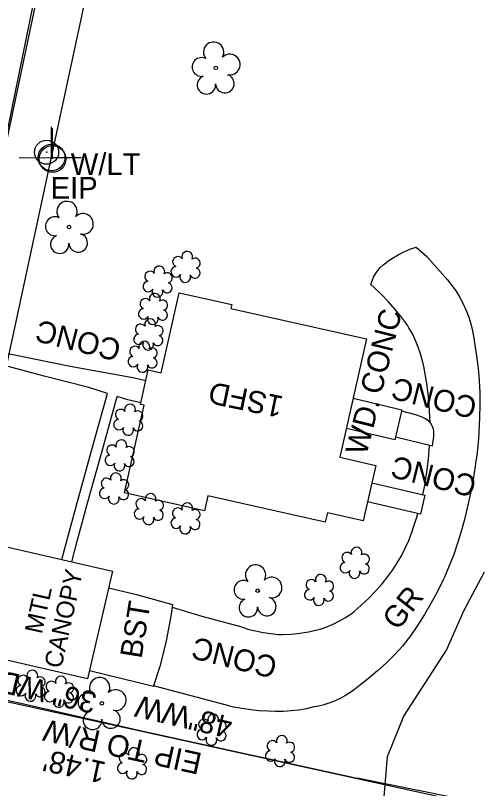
# Model space of a CAD drawing. Extents: x 1614611 to 1617571, y 898867 to 905462.
# Drawn here: x 1616539.4 to 1616625, y 901015.6 to 901157.4 of the extents above; entities that cross this region are included whole.
import ezdxf

# ---------------------------------------------------------------- set-up
doc = ezdxf.new("R2010")
doc.units = 0
for name, color, linetype in [('Exist Building', 7, 'Continuous'), ('Exist Building Metal Canopy', 7, 'Continuous'), ('Exist Building Metal Canopy Text', 7, 'Continuous'), ('Exist Building Text', 7, 'Continuous'), ('Exist Drainage Structure Drop Inlet CELL', 7, 'Continuous'), ('Exist Other Culture Area Outline', 7, 'Continuous'), ('Exist Other Culture Area Outline Text', 7, 'Continuous'), ('Exist Other Culture Fence Line', 7, 'Continuous'), ('Exist Other Culture Fence Line Text', 7, 'Continuous'), ('Exist Plan Preparation Watershed Yellow', 7, 'Continuous'), ('Exist Roads EOP Other Text', 7, 'Continuous'), ('Exist Roads Soil', 7, 'Continuous'), ('Exist Roads Soil Text', 7, 'Continuous'), ('Exist Utilities Power Joint Use Telephone CELL', 7, 'Continuous'), ('Exist Utilities Power Pole CELL', 7, 'Continuous'), ('Exist Utilities Power Pole Text', 7, 'Continuous'), ('Exist Utilities Sanitary Sewer UG Line', 7, 'Continuous'), ('Exist Utilities Telephone UG FO SUE LOS B', 7, 'Continuous'), ('Exist Vegetation Shrub CELL', 7, 'Continuous'), ('Exist Vegetation Tree CELL', 7, 'Continuous'), ('Exist Vegetation Woods Line', 7, 'Continuous'), ('Prop Drainage Structure Catch Basin Open Throat 4 Label', 7, 'Continuous'), ('Prop Drainage Structure Pipe Alternate 30in Label', 7, 'Continuous'), ('Prop Earthen Structure Head Ditch Label', 7, 'Continuous'), ('Scratch_Level_1', 7, 'Continuous')]:
    doc.layers.add(name, color=color, linetype=linetype)

msp = doc.modelspace()

# ---------------------------------------------------------------- linework, layer by layer
at = {"layer": 'Exist Building'}
msp.add_lwpolyline([(1616603.72, 901098.1), (1616598.85, 901076.36), (1616605.42, 901074.89), (1616603.14, 901064.73), (1616596.57, 901066.21), (1616596.19, 901064.49), (1616574.67, 901069.31), (1616574.06, 901066.58), (1616559.42, 901069.86), (1616563.02, 901085.9), (1616562.3, 901086.06), (1616563.71, 901092.37), (1616566.12, 901091.83), (1616569.41, 901106.5), (1616579.03, 901104.35), (1616578.87, 901103.67)], close=True, dxfattribs=at)
at = {"layer": 'Exist Building Metal Canopy'}
msp.add_lwpolyline([(1616537.54, 901060.03), (1616557.18, 901055.5), (1616552.62, 901035.75), (1616532.98, 901040.28)], close=True, dxfattribs=at)
at = {"layer": 'Exist Other Culture Area Outline'}
for points in [[(1616556.26, 901088.08), (1616552.83, 901089.13), (1616544.7, 901091.24), (1616535.73, 901093.64), (1616536.2, 901095.73), (1616549.45, 901093.07), (1616560.94, 901090.97), (1616563.28, 901090.43)], [(1616547.93, 901057.63), (1616548.95, 901061.47), (1616550.91, 901068.69), (1616553.74, 901078.87), (1616556.26, 901088.08)], [(1616549.74, 901057.22), (1616550.74, 901060.99), (1616552.7, 901068.2), (1616555.52, 901078.38), (1616558.03, 901087.54)], [(1616562.37, 901086.37), (1616560.02, 901086.92), (1616558.03, 901087.54)], [(1616601.28, 901087.19), (1616610.24, 901085.06), (1616608.93, 901079.54), (1616600.04, 901081.66)], [(1616609.06, 901080.1), (1616615.8, 901078.48), (1616616.05, 901080.2), (1616616.09, 901080.69), (1616616.06, 901081.19), (1616615.95, 901081.68), (1616615.76, 901082.14), (1616615.5, 901082.57), (1616615.17, 901082.95), (1616615.13, 901082.99), (1616614.55, 901083.39), (1616613.93, 901083.73), (1616613.28, 901083.99), (1616612.75, 901084.15), (1616610.18, 901084.81)], [(1616604.7, 901071.67), (1616614.41, 901069.45), (1616613.61, 901065.97), (1616603.92, 901068.19)]]:
    msp.add_lwpolyline(points, dxfattribs=at)
at = {"layer": 'Exist Other Culture Fence Line'}
for points in [[(1616524.45, 901034.81), (1616540.38, 901031.29), (1616562.24, 901026.28), (1616602, 901017.55)], [(1616668.58, 901003.27), (1616635.85, 901010.68), (1616602, 901017.55)]]:
    msp.add_lwpolyline(points, dxfattribs=at)
at = {"layer": 'Exist Plan Preparation Watershed Yellow'}
for radius in [2.2, 0.0707]:
    msp.add_circle((1616545.12, 901132.28), radius, dxfattribs=at)
at = {"layer": 'Exist Roads Soil'}
for points in [[(1616615.4, 901082.69), (1616615.37, 901083.78), (1616615.24, 901085.94), (1616615.03, 901088.09), (1616614.74, 901090.23), (1616614.37, 901092.36), (1616614.29, 901092.79), (1616614.01, 901094.07), (1616613.65, 901095.34), (1616613.23, 901096.58), (1616612.72, 901097.79), (1616612.15, 901098.97), (1616611.51, 901100.11), (1616611.23, 901100.56), (1616610.12, 901102.03), (1616608.96, 901103.47), (1616607.74, 901104.85), (1616606.46, 901106.2), (1616605.13, 901107.49), (1616604.55, 901108.02), (1616604.75, 901108.71), (1616605.03, 901109.38), (1616605.37, 901110.02), (1616605.79, 901110.62), (1616606.26, 901111.17), (1616606.79, 901111.66), (1616607.37, 901112.1), (1616607.48, 901112.17), (1616608.48, 901112.86), (1616609.52, 901113.48), (1616610.59, 901114.03), (1616611.7, 901114.51), (1616612.81, 901114.9), (1616614.76, 901113.15), (1616618.59, 901108.92), (1616619.4, 901107.88), (1616620.15, 901106.8), (1616620.84, 901105.67), (1616621.45, 901104.5), (1616622, 901103.3), (1616622.47, 901102.07), (1616622.86, 901100.8), (1616623.18, 901099.52), (1616623.42, 901098.22), (1616623.91, 901094.92), (1616624.18, 901092.68), (1616624.37, 901090.44), (1616624.48, 901088.19), (1616624.52, 901085.93), (1616624.47, 901083.68), (1616624.4, 901082.27), (1616624.23, 901079.76), (1616623.99, 901077.26), (1616623.67, 901074.76), (1616623.27, 901072.28), (1616622.79, 901069.81), (1616622.24, 901067.36), (1616622.18, 901067.11), (1616621.68, 901064.94), (1616621.1, 901062.79), (1616620.44, 901060.65), (1616619.71, 901058.55), (1616618.9, 901056.47), (1616618.02, 901054.42), (1616617.72, 901053.76), (1616616.67, 901051.65), (1616615.55, 901049.58), (1616614.37, 901047.55), (1616613.11, 901045.56), (1616611.79, 901043.61), (1616610.33, 901041.75), (1616608.89, 901040.15), (1616607.34, 901038.65), (1616605.74, 901037.2), (1616604.09, 901035.81), (1616602.39, 901034.48), (1616601.77, 901034.01), (1616600.86, 901033.33), (1616599.91, 901032.71), (1616598.92, 901032.16), (1616597.89, 901031.68), (1616596.82, 901031.28), (1616595.74, 901030.95), (1616594.63, 901030.7), (1616594.1, 901030.6), (1616592.72, 901030.28), (1616591.32, 901030.04), (1616589.91, 901029.88), (1616588.49, 901029.79), (1616587.07, 901029.79), (1616585.67, 901029.86), (1616584.09, 901029.92), (1616582.51, 901030.06), (1616580.95, 901030.29), (1616579.39, 901030.59), (1616577.85, 901030.97), (1616564.72, 901034.45)], [(1616614.06, 901069.54), (1616614.42, 901071.21), (1616614.79, 901073.62), (1616615.07, 901076.03), (1616615.27, 901078.45), (1616615.28, 901078.61)], [(1616568.11, 901048.91), (1616573.54, 901047.25), (1616580.66, 901045.32), (1616582.01, 901044.89), (1616583.39, 901044.53), (1616584.78, 901044.24), (1616586.19, 901044.04), (1616587.61, 901043.91), (1616588.34, 901043.88), (1616589.94, 901043.97), (1616591.53, 901044.14), (1616593.12, 901044.4), (1616594.69, 901044.73), (1616595.23, 901044.86), (1616596.44, 901045.29), (1616597.62, 901045.79), (1616598.76, 901046.36), (1616599.87, 901047), (1616600.93, 901047.7), (1616601.39, 901048.04), (1616602.78, 901049.25), (1616604.11, 901050.51), (1616605.38, 901051.83), (1616606.6, 901053.2), (1616607.64, 901054.49), (1616608.55, 901055.73), (1616609.38, 901057.01), (1616610.15, 901058.33), (1616610.84, 901059.69), (1616611.47, 901061.09), (1616611.6, 901061.4), (1616612.31, 901063.37), (1616612.96, 901065.37), (1616613.16, 901066.07)]]:
    msp.add_lwpolyline(points, dxfattribs=at)
at = {"layer": 'Exist Utilities Power Joint Use Telephone CELL'}
msp.add_line((1616546.03, 901131.31), (1616546.03, 901131.31), dxfattribs=at)
msp.add_lwpolyline([(1616540.09, 901131.31), (1616551.43, 901131.28), (1616546.03, 901131.29), (1616546.03, 901136.94)], dxfattribs=at)
msp.add_circle((1616546.03, 901131.32), 2.45, dxfattribs=at)
at = {"layer": 'Exist Utilities Power Pole CELL'}
for q in [(1616546.2, 901136.69), (1616546.2, 901131.06)]:
    msp.add_line((1616546.2, 901131.06), q, dxfattribs=at)
msp.add_circle((1616546.2, 901131.06), 2.45, dxfattribs=at)
at = {"layer": 'Exist Utilities Sanitary Sewer UG Line'}
msp.add_lwpolyline([(1616444.8, 900682.93), (1616490.78, 900905.02), (1616557.11, 901230.35), (1616512.18, 901240.77)], dxfattribs=at)
at = {"layer": 'Exist Utilities Telephone UG FO SUE LOS B'}
msp.add_lwpolyline([(1616361.31, 900327.32), (1616372.74, 900375.18), (1616381.89, 900419.08), (1616391.52, 900460.55), (1616402.98, 900510.37), (1616412.32, 900555.07), (1616423.47, 900606.59), (1616437.64, 900664.03), (1616444.4, 900703.78), (1616454.35, 900748.64), (1616464.75, 900795.88), (1616474.48, 900841.84), (1616484.09, 900886.8), (1616494.25, 900933.3), (1616504.35, 900979.92), (1616517.65, 901036.02), (1616527.27, 901079.83), (1616535.79, 901125.09), (1616545.13, 901168.85)], dxfattribs=at)
at = {"layer": 'Exist Vegetation Shrub CELL'}
for p, q in [((1616570.66, 901111.08), (1616570.66, 901111.08)), ((1616565.55, 901108.39), (1616565.55, 901108.39)), ((1616564.71, 901103.38), (1616564.71, 901103.38)), ((1616563.86, 901098.7), (1616563.86, 901098.7)), ((1616562.8, 901094.62), (1616562.8, 901094.62)), ((1616560.18, 901083.06), (1616560.18, 901083.06)), ((1616558.59, 901076.52), (1616558.59, 901076.52)), ((1616557.57, 901070.46), (1616557.57, 901070.46)), ((1616563.94, 901066.69), (1616563.94, 901066.69)), ((1616570.65, 901064.99), (1616570.65, 901064.99)), ((1616601.67, 901056.84), (1616601.67, 901056.84)), ((1616595.12, 901051.87), (1616595.12, 901051.87)), ((1616542.28, 901034.32), (1616542.28, 901034.32)), ((1616547.49, 901033.21), (1616547.49, 901033.21)), ((1616575.43, 901026.25), (1616575.43, 901026.25)), ((1616587.98, 901022.33), (1616587.98, 901022.33)), ((1616560.87, 901020.09), (1616560.87, 901020.09))]:
    msp.add_line(p, q, dxfattribs=at)
for centre, radius, start, end in [((1616569.18, 901112.21), 0.968, 35.8908, 245.4216), ((1616570.89, 901113.12), 0.99, 334.8391, 200.4717), ((1616572.33, 901111.95), 0.929, 284.4567, 126.0861), ((1616564.07, 901109.52), 0.968, 35.8908, 245.4216), ((1616565.78, 901110.43), 0.99, 334.8391, 200.4717), ((1616568.86, 901110.37), 0.955, 95.1099, 327.9534), ((1616572.3, 901110.15), 0.937, 204.9913, 73.4601), ((1616567.22, 901109.26), 0.929, 284.4567, 126.0861), ((1616570.53, 901109.4), 0.984, 151.2797, 21.387), ((1616563.75, 901107.68), 0.955, 95.1099, 327.9534), ((1616567.19, 901107.46), 0.937, 204.9913, 73.4601), ((1616564.94, 901105.42), 0.99, 334.8391, 200.4717), ((1616565.42, 901106.7), 0.984, 151.2797, 21.387), ((1616563.22, 901104.5), 0.968, 35.8908, 245.4216), ((1616566.38, 901104.25), 0.929, 284.4567, 126.0861), ((1616562.91, 901102.67), 0.955, 95.1099, 327.9534), ((1616566.34, 901102.45), 0.937, 204.9913, 73.4601), ((1616564.09, 901100.74), 0.99, 334.8391, 200.4717), ((1616564.58, 901101.69), 0.984, 151.2797, 21.387), ((1616562.37, 901099.82), 0.968, 35.8908, 245.4216), ((1616565.53, 901099.57), 0.929, 284.4567, 126.0861), ((1616562.06, 901097.99), 0.955, 95.1099, 327.9534), ((1616563.03, 901096.66), 0.99, 334.8391, 200.4717), ((1616563.73, 901097.01), 0.984, 151.2797, 21.387), ((1616565.49, 901097.77), 0.937, 204.9913, 73.4601), ((1616561.32, 901095.75), 0.968, 35.8908, 245.4216), ((1616564.47, 901095.49), 0.929, 284.4567, 126.0861), ((1616561, 901093.92), 0.955, 95.1099, 327.9534), ((1616562.67, 901092.94), 0.984, 151.2797, 21.387), ((1616564.44, 901093.69), 0.937, 204.9913, 73.4601), ((1616558.7, 901084.19), 0.968, 35.8908, 245.4216), ((1616560.41, 901085.11), 0.99, 334.8391, 200.4717), ((1616561.85, 901083.93), 0.929, 284.4567, 126.0861), ((1616558.38, 901082.36), 0.955, 95.1099, 327.9534), ((1616560.05, 901081.38), 0.984, 151.2797, 21.387), ((1616561.81, 901082.14), 0.937, 204.9913, 73.4601), ((1616558.82, 901078.56), 0.99, 334.8391, 200.4717), ((1616557.11, 901077.65), 0.968, 35.8908, 245.4216), ((1616560.26, 901077.39), 0.929, 284.4567, 126.0861), ((1616556.79, 901075.82), 0.955, 95.1099, 327.9534), ((1616560.23, 901075.59), 0.937, 204.9913, 73.4601), ((1616558.46, 901074.84), 0.984, 151.2797, 21.387), ((1616557.8, 901072.5), 0.99, 334.8391, 200.4717), ((1616556.09, 901071.59), 0.968, 35.8908, 245.4216), ((1616559.25, 901071.33), 0.929, 284.4567, 126.0861), ((1616555.77, 901069.76), 0.955, 95.1099, 327.9534), ((1616557.44, 901068.78), 0.984, 151.2797, 21.387), ((1616559.21, 901069.53), 0.937, 204.9913, 73.4601), ((1616564.16, 901068.73), 0.99, 334.8391, 200.4717), ((1616562.45, 901067.82), 0.968, 35.8908, 245.4216), ((1616565.61, 901067.56), 0.929, 284.4567, 126.0861), ((1616570.87, 901067.03), 0.99, 334.8391, 200.4717), ((1616562.14, 901065.98), 0.955, 95.1099, 327.9534), ((1616565.57, 901065.76), 0.937, 204.9913, 73.4601), ((1616569.16, 901066.12), 0.968, 35.8908, 245.4216), ((1616572.32, 901065.86), 0.929, 284.4567, 126.0861), ((1616563.81, 901065), 0.984, 151.2797, 21.387), ((1616568.85, 901064.29), 0.955, 95.1099, 327.9534), ((1616572.28, 901064.06), 0.937, 204.9913, 73.4601), ((1616570.52, 901063.31), 0.984, 151.2797, 21.387), ((1616601.9, 901058.88), 0.99, 334.8391, 200.4717), ((1616600.19, 901057.97), 0.968, 35.8908, 245.4216), ((1616603.34, 901057.71), 0.929, 284.4567, 126.0861), ((1616599.87, 901056.14), 0.955, 95.1099, 327.9534), ((1616603.31, 901055.92), 0.937, 204.9913, 73.4601), ((1616601.54, 901055.16), 0.984, 151.2797, 21.387), ((1616593.63, 901053), 0.968, 35.8908, 245.4216), ((1616595.35, 901053.91), 0.99, 334.8391, 200.4717), ((1616596.79, 901052.74), 0.929, 284.4567, 126.0861), ((1616593.32, 901051.17), 0.955, 95.1099, 327.9534), ((1616596.75, 901050.95), 0.937, 204.9913, 73.4601), ((1616594.99, 901050.19), 0.984, 151.2797, 21.387), ((1616542.5, 901036.36), 0.99, 334.8391, 200.4717), ((1616540.79, 901035.45), 0.968, 35.8908, 245.4216), ((1616543.95, 901035.19), 0.929, 284.4567, 126.0861), ((1616546, 901034.34), 0.968, 35.8908, 245.4216), ((1616547.71, 901035.25), 0.99, 334.8391, 200.4717), ((1616540.48, 901033.62), 0.955, 95.1099, 327.9534), ((1616543.91, 901033.4), 0.937, 204.9913, 73.4601), ((1616549.16, 901034.08), 0.929, 284.4567, 126.0861), ((1616542.15, 901032.64), 0.984, 151.2797, 21.387), ((1616545.68, 901032.5), 0.955, 95.1099, 327.9534), ((1616549.12, 901032.28), 0.937, 204.9913, 73.4601), ((1616547.36, 901031.52), 0.984, 151.2797, 21.387), ((1616573.94, 901027.38), 0.968, 35.8908, 245.4216), ((1616575.66, 901028.3), 0.99, 334.8391, 200.4717), ((1616577.1, 901027.12), 0.929, 284.4567, 126.0861), ((1616573.63, 901025.55), 0.955, 95.1099, 327.9534), ((1616577.06, 901025.33), 0.937, 204.9913, 73.4601), ((1616588.21, 901024.37), 0.99, 334.8391, 200.4717), ((1616575.3, 901024.57), 0.984, 151.2797, 21.387), ((1616586.5, 901023.46), 0.968, 35.8908, 245.4216), ((1616589.65, 901023.2), 0.929, 284.4567, 126.0861), ((1616561.1, 901022.13), 0.99, 334.8391, 200.4717), ((1616586.18, 901021.63), 0.955, 95.1099, 327.9534), ((1616559.39, 901021.21), 0.968, 35.8908, 245.4216), ((1616562.55, 901020.96), 0.929, 284.4567, 126.0861), ((1616587.85, 901020.65), 0.984, 151.2797, 21.387), ((1616589.62, 901021.4), 0.937, 204.9913, 73.4601), ((1616559.07, 901019.38), 0.955, 95.1099, 327.9534), ((1616562.51, 901019.16), 0.937, 204.9913, 73.4601), ((1616560.74, 901018.4), 0.984, 151.2797, 21.387)]:
    msp.add_arc(centre, radius, start, end, dxfattribs=at)
at = {"layer": 'Exist Vegetation Tree CELL'}
for p, q in [((1616576.12, 901147.76), (1616576.12, 901147.76)), ((1616549.23, 901118.56), (1616549.23, 901118.56)), ((1616583.8, 901051.91), (1616583.8, 901051.91)), ((1616555.24, 901031.28), (1616555.24, 901031.28))]:
    msp.add_line(p, q, dxfattribs=at)
for centre in [(1616576.12, 901147.76), (1616549.23, 901118.56), (1616583.8, 901051.91), (1616555.24, 901031.28)]:
    msp.add_circle(centre, 0.326, dxfattribs=at)
for centre, radius, start, end in [((1616575.73, 901150.63), 1.86, 330.1651, 219.7134), ((1616578.67, 901148.35), 1.9, 257.1011, 134.1999), ((1616573.51, 901147.91), 1.73, 62.6636, 279.3457), ((1616574.41, 901144.64), 1.69, 111.5671, 6.231), ((1616577.79, 901144.86), 1.7, 181.2822, 74.56), ((1616548.85, 901121.43), 1.86, 330.1651, 219.7134), ((1616546.63, 901118.71), 1.73, 62.6636, 279.3457), ((1616551.78, 901119.14), 1.9, 257.1011, 134.1999), ((1616550.91, 901115.66), 1.7, 181.2822, 74.56), ((1616547.53, 901115.43), 1.69, 111.5671, 6.231), ((1616583.41, 901054.78), 1.86, 330.1651, 219.7134), ((1616581.19, 901052.06), 1.73, 62.6636, 279.3457), ((1616586.35, 901052.5), 1.9, 257.1011, 134.1999), ((1616582.09, 901048.79), 1.69, 111.5671, 6.231), ((1616585.47, 901049.01), 1.7, 181.2822, 74.56), ((1616554.85, 901034.15), 1.86, 330.1651, 219.7134), ((1616557.79, 901031.86), 1.9, 257.1011, 134.1999), ((1616552.63, 901031.43), 1.73, 62.6636, 279.3457), ((1616553.53, 901028.15), 1.69, 111.5671, 6.231), ((1616556.91, 901028.38), 1.7, 181.2822, 74.56)]:
    msp.add_arc(centre, radius, start, end, dxfattribs=at)
at = {"layer": 'Exist Vegetation Woods Line'}
msp.add_lwpolyline([(1616578.08, 900924.6), (1616585.16, 900931.92), (1616591.83, 900939.06), (1616595.38, 900947.14), (1616603.49, 900961.25), (1616608.72, 900981.57), (1616609.36, 900996.67), (1616607.6, 901006.43), (1616606.87, 901012.68), (1616607.56, 901021.52), (1616610.57, 901028.93), (1616618.38, 901041.02), (1616621.6, 901048.23), (1616625.37, 901055.39)], dxfattribs=at)
at = {"layer": 'Prop Drainage Structure Pipe Alternate 30in Label'}
msp.add_line((1616525.06, 901034.36), (1616968.37, 900937.26), dxfattribs=at)
at = {"layer": 'Prop Earthen Structure Head Ditch Label'}
msp.add_line((1616609.17, 901425.29), (1616459.79, 900731.01), dxfattribs=at)
at = {"layer": 'Scratch_Level_1'}
msp.add_lwpolyline([(1616556.47, 901052.46), (1616561.61, 901051.19), (1616568.16, 901049.41), (1616568.11, 901048.91), (1616567.91, 901047.25), (1616567, 901042.72), (1616565.94, 901038.21), (1616564.72, 901034.45), (1616564.68, 901034.35), (1616552.96, 901037.22)], dxfattribs=at)

# ---------------------------------------------------------------- texts
at = {"layer": 'Exist Building Metal Canopy Text'}
for s, p in [('CANOPY', (1616547.81, 901037.52)), ('MTL ', (1616544.24, 901043.85))]:
    msp.add_text(s, height=3.24, rotation=77.4737, dxfattribs=at).set_placement(p)
at = {"layer": 'Exist Building Text'}
msp.add_text('1SFD', height=4, rotation=168.3329, dxfattribs=at).set_placement((1616588.7, 901087.48))
at = {"layer": 'Exist Drainage Structure Drop Inlet CELL'}
msp.add_text('EIP', height=4, dxfattribs=at).set_placement((1616545.86, 901123.77))
at = {"layer": 'Exist Other Culture Area Outline Text'}
for s, rotation, p in [('CONC', 75.8866, (1616606.41, 901087.67)), ('CONC', 165.8866, (1616559.03, 901097.77)), ('CONC', 165.8866, (1616624.25, 901087.22)), ('WD.', 75.8866, (1616603.71, 901076.55)), ('CONC', 165.8866, (1616624.16, 901072.85)), ('CONC', 165.8866, (1616587.64, 901039.64))]:
    msp.add_text(s, height=4, rotation=rotation, dxfattribs=at).set_placement(p)
at = {"layer": 'Exist Other Culture Fence Line Text'}
for s, p in [('36" WD', (1616554.55, 901033.2)), ('48"WW', (1616579.43, 901028.69))]:
    msp.add_text(s, height=4, rotation=166.8452, dxfattribs=at).set_placement(p)
at = {"layer": 'Exist Roads EOP Other Text'}
msp.add_text('BST', height=4, rotation=80.7568, dxfattribs=at).set_placement((1616562.5, 901039.34))
at = {"layer": 'Exist Roads Soil Text'}
msp.add_text('GR', height=4, rotation=51.8988, dxfattribs=at).set_placement((1616609.47, 901044.44))
at = {"layer": 'Exist Utilities Power Pole Text'}
msp.add_text('W/LT', height=4, dxfattribs=at).set_placement((1616549.54, 901128.1))
at = {"layer": 'Prop Drainage Structure Catch Basin Open Throat 4 Label'}
for s, p in [('EIP TO R/W', (1616573.81, 901022.08)), ("1.48'", (1616556.21, 901020.42))]:
    msp.add_text(s, height=4, rotation=167.6446, dxfattribs=at).set_placement(p)

doc.saveas('drawing.dxf')
